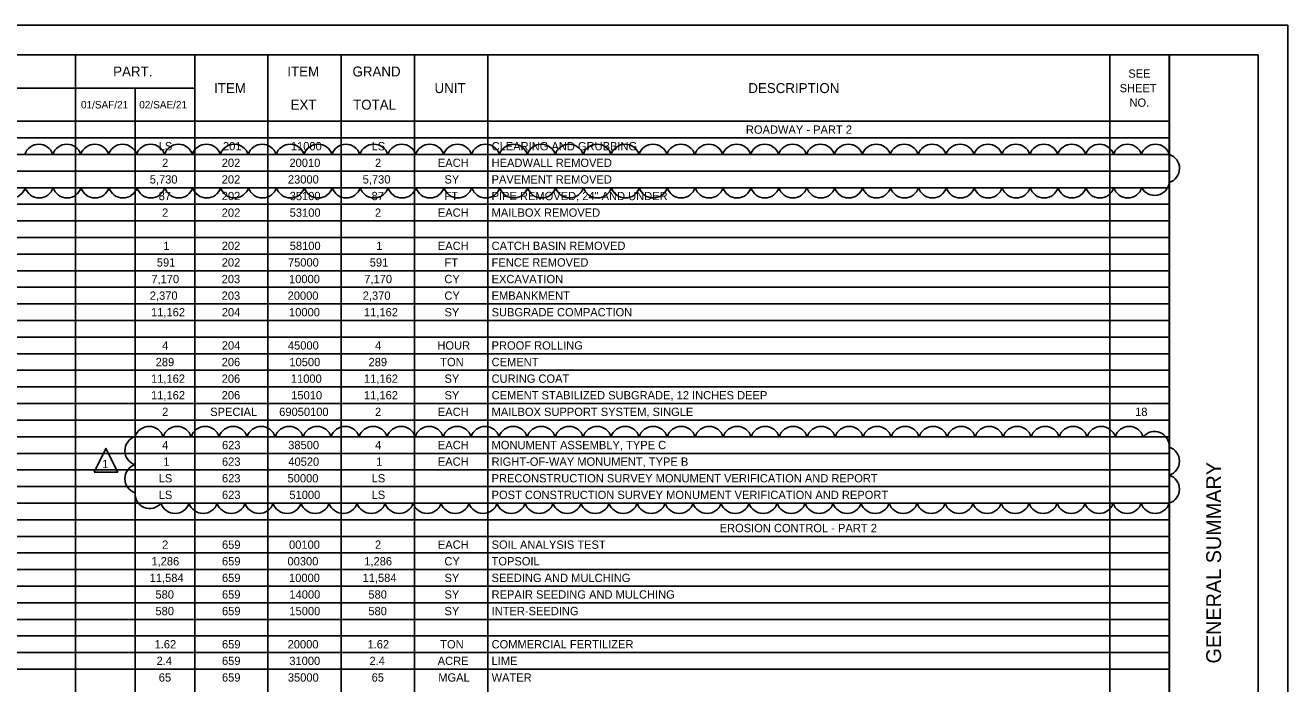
# Model space of a CAD drawing. Extents: x -156 to 77, y 0 to 24.
# Drawn here: x 12.71 to 34, y 10.89 to 22 of the extents above; entities that cross this region are included whole.
import ezdxf

# ---------------------------------------------------------------- set-up
doc = ezdxf.new("R2010")
doc.units = 0
for name, color, linetype in [('Default', 7, 'Continuous'), ('MU_Markup_Cloud', 7, 'Continuous'), ('SH_Border', 7, 'Continuous'), ('SH_Cut_Line', 7, 'Continuous'), ('SH_Data', 7, 'Continuous')]:
    doc.layers.add(name, color=color, linetype=linetype)

msp = doc.modelspace()

# ---------------------------------------------------------------- linework, layer by layer
at = {"layer": 'Default'}
for p, q in [((1.5, 21.5), (32.004, 21.5)), ((13.556, 21.5), (13.556, 0.5)), ((15.566, 21.5), (15.566, 0.5)), ((16.801, 21.5), (16.801, 0.5)), ((18.036, 21.5), (18.036, 0.5)), ((19.272, 21.5), (19.272, 0.5)), ((20.507, 21.5), (20.507, 0.5)), ((30.999, 21.5), (30.999, 0.5)), ((32.004, 21.5), (32.004, 0.5)), ((1.5, 20.94), (15.566, 20.94)), ((14.561, 20.94), (14.561, 0.5)), ((1.5, 20.38), (32.004, 20.38)), ((1.5, 20.1), (32.004, 20.1)), ((1.5, 19.82), (32.004, 19.82)), ((1.5, 19.54), (32.004, 19.54)), ((1.5, 19.26), (32.004, 19.26)), ((1.5, 18.98), (32.004, 18.98)), ((1.5, 18.7), (32.004, 18.7)), ((1.5, 18.42), (32.004, 18.42)), ((1.5, 18.14), (32.004, 18.14)), ((1.5, 17.86), (32.004, 17.86)), ((1.5, 17.58), (32.004, 17.58)), ((1.5, 17.3), (32.004, 17.3)), ((1.5, 17.02), (32.004, 17.02)), ((1.5, 16.74), (32.004, 16.74)), ((1.5, 16.46), (32.004, 16.46)), ((1.5, 16.18), (32.004, 16.18)), ((1.5, 15.9), (32.004, 15.9)), ((1.5, 15.62), (32.004, 15.62)), ((1.5, 15.34), (32.004, 15.34)), ((1.5, 15.06), (32.004, 15.06)), ((1.5, 14.78), (32.004, 14.78)), ((1.5, 14.5), (32.004, 14.5)), ((1.5, 14.22), (32.004, 14.22)), ((1.5, 13.94), (32.004, 13.94)), ((1.5, 13.66), (32.004, 13.66)), ((1.5, 13.38), (32.004, 13.38)), ((1.5, 13.1), (32.004, 13.1)), ((1.5, 12.82), (32.004, 12.82)), ((1.5, 12.54), (32.004, 12.54)), ((1.5, 12.26), (32.004, 12.26)), ((1.5, 11.98), (32.004, 11.98)), ((1.5, 11.7), (32.004, 11.7)), ((1.5, 11.42), (32.004, 11.42)), ((1.5, 11.14), (32.004, 11.14))]:
    msp.add_line(p, q, dxfattribs=at)
at = {"layer": 'MU_Markup_Cloud'}
msp.add_lwpolyline([(13.869, 14.464), (14.069, 14.864), (14.269, 14.464)], close=True, dxfattribs=at)
for centre, radius, start, end in [((12.938, 19.746), 0.247, 17.5, 162.5), ((13.409, 19.746), 0.247, 17.5, 162.5), ((13.88, 19.746), 0.247, 17.5, 162.5), ((14.35, 19.746), 0.247, 17.5, 162.5), ((14.821, 19.746), 0.247, 17.5, 162.5), ((15.292, 19.746), 0.247, 17.5, 162.5), ((15.763, 19.746), 0.247, 17.5, 162.5), ((16.233, 19.746), 0.247, 17.5, 162.5), ((16.704, 19.746), 0.247, 17.5, 162.5), ((17.175, 19.746), 0.247, 17.5, 162.5), ((17.646, 19.746), 0.247, 17.5, 162.5), ((18.116, 19.746), 0.247, 17.5, 162.5), ((18.587, 19.746), 0.247, 17.5, 162.5), ((19.058, 19.746), 0.247, 17.5, 162.5), ((19.529, 19.746), 0.247, 17.5, 162.5), ((19.999, 19.746), 0.247, 17.5, 162.5), ((20.47, 19.746), 0.247, 17.5, 162.5), ((20.941, 19.746), 0.247, 17.5, 162.5), ((21.412, 19.746), 0.247, 17.5, 162.5), ((21.882, 19.746), 0.247, 17.5, 162.5), ((22.353, 19.746), 0.247, 17.5, 162.5), ((22.824, 19.746), 0.247, 17.5, 162.5), ((23.295, 19.746), 0.247, 17.5, 162.5), ((23.765, 19.746), 0.247, 17.5, 162.5), ((24.236, 19.746), 0.247, 17.5, 162.5), ((24.707, 19.746), 0.247, 17.5, 162.5), ((25.178, 19.746), 0.247, 17.5, 162.5), ((25.648, 19.746), 0.247, 17.5, 162.5), ((26.119, 19.746), 0.247, 17.5, 162.5), ((26.59, 19.746), 0.247, 17.5, 162.5), ((27.061, 19.746), 0.247, 17.5, 162.5), ((27.531, 19.746), 0.247, 17.5, 162.5), ((28.002, 19.746), 0.247, 17.5, 162.5), ((28.473, 19.746), 0.247, 17.5, 162.5), ((28.944, 19.746), 0.247, 17.5, 162.5), ((29.414, 19.746), 0.247, 17.5, 162.5), ((29.885, 19.746), 0.247, 17.5, 162.5), ((30.356, 19.746), 0.247, 17.5, 162.5), ((30.827, 19.746), 0.247, 17.5, 162.5), ((31.297, 19.746), 0.247, 17.5, 162.5), ((31.768, 19.746), 0.247, 17.5, 162.5), ((31.928, 19.585), 0.247, 287.1367, 72.1367), ((12.473, 19.334), 0.247, 197.5, 342.5), ((12.944, 19.334), 0.247, 197.5, 342.5), ((13.414, 19.334), 0.247, 197.5, 342.5), ((13.885, 19.334), 0.247, 197.5, 342.5), ((14.356, 19.334), 0.247, 197.5, 342.5), ((14.827, 19.334), 0.247, 197.5, 342.5), ((15.297, 19.334), 0.247, 197.5, 342.5), ((15.768, 19.334), 0.247, 197.5, 342.5), ((16.239, 19.334), 0.247, 197.5, 342.5), ((16.71, 19.334), 0.247, 197.5, 342.5), ((17.18, 19.334), 0.247, 197.5, 342.5), ((17.651, 19.334), 0.247, 197.5, 342.5), ((18.122, 19.334), 0.247, 197.5, 342.5), ((18.593, 19.334), 0.247, 197.5, 342.5), ((19.063, 19.334), 0.247, 197.5, 342.5), ((19.534, 19.334), 0.247, 197.5, 342.5), ((20.005, 19.334), 0.247, 197.5, 342.5), ((20.476, 19.334), 0.247, 197.5, 342.5), ((20.946, 19.334), 0.247, 197.5, 342.5), ((21.417, 19.334), 0.247, 197.5, 342.5), ((21.888, 19.334), 0.247, 197.5, 342.5), ((22.359, 19.334), 0.247, 197.5, 342.5), ((22.829, 19.334), 0.247, 197.5, 342.5), ((23.3, 19.334), 0.247, 197.5, 342.5), ((23.771, 19.334), 0.247, 197.5, 342.5), ((24.242, 19.334), 0.247, 197.5, 342.5), ((24.712, 19.334), 0.247, 197.5, 342.5), ((25.183, 19.334), 0.247, 197.5, 342.5), ((25.654, 19.334), 0.247, 197.5, 342.5), ((26.125, 19.334), 0.247, 197.5, 342.5), ((26.595, 19.334), 0.247, 197.5, 342.5), ((27.066, 19.334), 0.247, 197.5, 342.5), ((27.537, 19.334), 0.247, 197.5, 342.5), ((28.008, 19.334), 0.247, 197.5, 342.5), ((28.478, 19.334), 0.247, 197.5, 342.5), ((28.949, 19.334), 0.247, 197.5, 342.5), ((29.42, 19.334), 0.247, 197.5, 342.5), ((29.891, 19.334), 0.247, 197.5, 342.5), ((30.361, 19.334), 0.247, 197.5, 342.5), ((30.832, 19.334), 0.247, 197.5, 342.5), ((31.303, 19.334), 0.247, 197.5, 342.5), ((31.755, 19.377), 0.247, 208.4302, 353.4302), ((14.797, 14.986), 0.248, 17.5, 162.5), ((15.27, 14.986), 0.248, 17.5, 162.5), ((15.742, 14.986), 0.248, 17.5, 162.5), ((16.214, 14.986), 0.248, 17.5, 162.5), ((16.686, 14.986), 0.248, 17.5, 162.5), ((17.159, 14.986), 0.248, 17.5, 162.5), ((17.631, 14.986), 0.248, 17.5, 162.5), ((18.103, 14.986), 0.248, 17.5, 162.5), ((18.575, 14.986), 0.248, 17.5, 162.5), ((19.047, 14.986), 0.248, 17.5, 162.5), ((19.52, 14.986), 0.248, 17.5, 162.5), ((19.992, 14.986), 0.248, 17.5, 162.5), ((20.464, 14.986), 0.248, 17.5, 162.5), ((20.936, 14.986), 0.248, 17.5, 162.5), ((21.409, 14.986), 0.248, 17.5, 162.5), ((21.881, 14.986), 0.248, 17.5, 162.5), ((22.353, 14.986), 0.248, 17.5, 162.5), ((22.825, 14.986), 0.248, 17.5, 162.5), ((23.298, 14.986), 0.248, 17.5, 162.5), ((23.77, 14.986), 0.248, 17.5, 162.5), ((24.242, 14.986), 0.248, 17.5, 162.5), ((24.714, 14.986), 0.248, 17.5, 162.5), ((25.187, 14.986), 0.248, 17.5, 162.5), ((25.659, 14.986), 0.248, 17.5, 162.5), ((26.131, 14.986), 0.248, 17.5, 162.5), ((26.603, 14.986), 0.248, 17.5, 162.5), ((27.076, 14.986), 0.248, 17.5, 162.5), ((27.548, 14.986), 0.248, 17.5, 162.5), ((28.02, 14.986), 0.248, 17.5, 162.5), ((28.492, 14.986), 0.248, 17.5, 162.5), ((28.965, 14.986), 0.248, 17.5, 162.5), ((29.437, 14.986), 0.248, 17.5, 162.5), ((29.909, 14.986), 0.248, 17.5, 162.5), ((30.381, 14.986), 0.248, 17.5, 162.5), ((30.854, 14.986), 0.248, 17.5, 162.5), ((31.326, 14.986), 0.248, 17.5, 162.5), ((31.753, 14.903), 0.247, 355.6683, 140.6683), ((14.636, 14.824), 0.248, 107.5, 252.5), ((31.926, 14.648), 0.248, 287.5, 72.5), ((14.636, 14.352), 0.248, 107.5, 252.5), ((31.926, 14.176), 0.248, 287.5, 72.5), ((14.808, 14.097), 0.247, 175.6683, 320.6683), ((15.235, 14.014), 0.248, 197.5, 342.5), ((15.708, 14.014), 0.248, 197.5, 342.5), ((16.18, 14.014), 0.248, 197.5, 342.5), ((16.652, 14.014), 0.248, 197.5, 342.5), ((17.124, 14.014), 0.248, 197.5, 342.5), ((17.597, 14.014), 0.248, 197.5, 342.5), ((18.069, 14.014), 0.248, 197.5, 342.5), ((18.541, 14.014), 0.248, 197.5, 342.5), ((19.013, 14.014), 0.248, 197.5, 342.5), ((19.486, 14.014), 0.248, 197.5, 342.5), ((19.958, 14.014), 0.248, 197.5, 342.5), ((20.43, 14.014), 0.248, 197.5, 342.5), ((20.902, 14.014), 0.248, 197.5, 342.5), ((21.375, 14.014), 0.248, 197.5, 342.5), ((21.847, 14.014), 0.248, 197.5, 342.5), ((22.319, 14.014), 0.248, 197.5, 342.5), ((22.791, 14.014), 0.248, 197.5, 342.5), ((23.264, 14.014), 0.248, 197.5, 342.5), ((23.736, 14.014), 0.248, 197.5, 342.5), ((24.208, 14.014), 0.248, 197.5, 342.5), ((24.68, 14.014), 0.248, 197.5, 342.5), ((25.152, 14.014), 0.248, 197.5, 342.5), ((25.625, 14.014), 0.248, 197.5, 342.5), ((26.097, 14.014), 0.248, 197.5, 342.5), ((26.569, 14.014), 0.248, 197.5, 342.5), ((27.041, 14.014), 0.248, 197.5, 342.5), ((27.514, 14.014), 0.248, 197.5, 342.5), ((27.986, 14.014), 0.248, 197.5, 342.5), ((28.458, 14.014), 0.248, 197.5, 342.5), ((28.93, 14.014), 0.248, 197.5, 342.5), ((29.403, 14.014), 0.248, 197.5, 342.5), ((29.875, 14.014), 0.248, 197.5, 342.5), ((30.347, 14.014), 0.248, 197.5, 342.5), ((30.819, 14.014), 0.248, 197.5, 342.5), ((31.292, 14.014), 0.248, 197.5, 342.5), ((31.764, 14.014), 0.248, 197.5, 342.5)]:
    msp.add_arc(centre, radius, start, end, dxfattribs=at)
at = {"layer": 'SH_Border'}
msp.add_line((32, 0.5), (32, 21.5), dxfattribs=at)
msp.add_lwpolyline([(1.5, 21.5), (33.5, 21.5), (33.5, 0.5), (1.5, 0.5)], close=True, dxfattribs=at)
at = {"layer": 'SH_Cut_Line'}
msp.add_lwpolyline([(0, 0), (34, 0), (34, 22), (0, 22)], close=True, dxfattribs=at)

# ---------------------------------------------------------------- texts
at = {"layer": 'Default'}
for s, height, p in [('PART.', 0.168, (14.191, 21.136)), ('ITEM', 0.168, (17.128, 21.136)), ('GRAND', 0.168, (18.227, 21.136)), ('SEE ', 0.14, (31.311, 21.115)), ('ITEM', 0.168, (15.893, 20.856)), ('UNIT', 0.168, (19.61, 20.856)), ('DESCRIPTION', 0.168, (24.903, 20.856)), ('SHEET ', 0.14, (31.165, 20.87)), ('01/SAF/21', 0.126, (13.648, 20.597)), ('02/SAE/21', 0.126, (14.631, 20.597)), ('EXT', 0.168, (17.183, 20.576)), ('TOTAL', 0.168, (18.237, 20.576)), ('NO.', 0.14, (31.331, 20.625)), ('ROADWAY - PART 2', 0.14, (24.862, 20.17)), ('LS', 0.14, (14.959, 19.89)), ('201', 0.14, (16.043, 19.89)), ('11000', 0.14, (17.188, 19.89)), ('LS', 0.14, (18.55, 19.89)), ('CLEARING AND GRUBBING', 0.14, (20.573, 19.89)), ('2', 0.14, (15.016, 19.61)), ('202', 0.14, (16.022, 19.61)), ('20010', 0.14, (17.164, 19.61)), ('2', 0.14, (18.607, 19.61)), ('EACH', 0.14, (19.667, 19.61)), ('HEADWALL REMOVED', 0.14, (20.573, 19.61)), ('5,730', 0.14, (14.808, 19.33)), ('202', 0.14, (16.022, 19.33)), ('23000', 0.14, (17.138, 19.33)), ('5,730', 0.14, (18.399, 19.33)), ('SY', 0.14, (19.779, 19.33)), ('PAVEMENT REMOVED', 0.14, (20.573, 19.33)), ('87', 0.14, (14.958, 19.05)), ('202', 0.14, (16.022, 19.05)), ('35100', 0.14, (17.168, 19.05)), ('87', 0.14, (18.548, 19.05)), ('FT', 0.14, (19.779, 19.05)), ('PIPE REMOVED, 24" AND UNDER', 0.14, (20.573, 19.05)), ('2', 0.14, (15.016, 18.77)), ('202', 0.14, (16.022, 18.77)), ('53100', 0.14, (17.168, 18.77)), ('2', 0.14, (18.607, 18.77)), ('EACH', 0.14, (19.667, 18.77)), ('MAILBOX REMOVED', 0.14, (20.573, 18.77)), ('1', 0.14, (15.037, 18.21)), ('202', 0.14, (16.022, 18.21)), ('58100', 0.14, (17.169, 18.21)), ('1', 0.14, (18.628, 18.21)), ('EACH', 0.14, (19.667, 18.21)), ('CATCH BASIN REMOVED', 0.14, (20.573, 18.21)), ('591', 0.14, (14.927, 17.93)), ('202', 0.14, (16.022, 17.93)), ('75000', 0.14, (17.139, 17.93)), ('591', 0.14, (18.518, 17.93)), ('FT', 0.14, (19.779, 17.93)), ('FENCE REMOVED', 0.14, (20.573, 17.93)), ('7,170', 0.14, (14.835, 17.65)), ('203', 0.14, (16.021, 17.65)), ('10000', 0.14, (17.157, 17.65)), ('7,170', 0.14, (18.426, 17.65)), ('CY', 0.14, (19.777, 17.65)), ('EXCAVATION', 0.14, (20.573, 17.65)), ('2,370', 0.14, (14.809, 17.37)), ('203', 0.14, (16.021, 17.37)), ('20000', 0.14, (17.133, 17.37)), ('2,370', 0.14, (18.4, 17.37)), ('CY', 0.14, (19.777, 17.37)), ('EMBANKMENT', 0.14, (20.573, 17.37)), ('11,162', 0.14, (14.83, 17.09)), ('204', 0.14, (16.023, 17.09)), ('10000', 0.14, (17.157, 17.09)), ('11,162', 0.14, (18.421, 17.09)), ('SY', 0.14, (19.779, 17.09)), ('SUBGRADE COMPACTION', 0.14, (20.573, 17.09)), ('4', 0.14, (15.017, 16.53)), ('204', 0.14, (16.023, 16.53)), ('45000', 0.14, (17.138, 16.53)), ('4', 0.14, (18.608, 16.53)), ('HOUR', 0.14, (19.659, 16.53)), ('PROOF ROLLING', 0.14, (20.573, 16.53)), ('289', 0.14, (14.908, 16.25)), ('206', 0.14, (16.021, 16.25)), ('10500', 0.14, (17.163, 16.25)), ('289', 0.14, (18.498, 16.25)), ('TON', 0.14, (19.707, 16.25)), ('CEMENT', 0.14, (20.573, 16.25)), ('11,162', 0.14, (14.83, 15.97)), ('206', 0.14, (16.021, 15.97)), ('11000', 0.14, (17.188, 15.97)), ('11,162', 0.14, (18.421, 15.97)), ('SY', 0.14, (19.779, 15.97)), ('CURING COAT', 0.14, (20.573, 15.97)), ('11,162', 0.14, (14.83, 15.69)), ('206', 0.14, (16.021, 15.69)), ('15010', 0.14, (17.194, 15.69)), ('11,162', 0.14, (18.421, 15.69)), ('SY', 0.14, (19.779, 15.69)), ('CEMENT STABILIZED SUBGRADE, 12 INCHES DEEP', 0.14, (20.573, 15.69)), ('2', 0.14, (15.016, 15.41)), ('SPECIAL', 0.14, (15.828, 15.41)), ('69050100', 0.14, (16.991, 15.41)), ('2', 0.14, (18.607, 15.41)), ('EACH', 0.14, (19.667, 15.41)), ('MAILBOX SUPPORT SYSTEM, SINGLE', 0.14, (20.573, 15.41)), ('18', 0.14, (31.426, 15.41)), ('4', 0.14, (15.017, 14.85)), ('623', 0.14, (16.026, 14.85)), ('38500', 0.14, (17.143, 14.85)), ('4', 0.14, (18.608, 14.85)), ('EACH', 0.14, (19.667, 14.85)), ('MONUMENT ASSEMBLY, TYPE C', 0.14, (20.573, 14.85)), ('1', 0.14, (15.037, 14.57)), ('623', 0.14, (16.026, 14.57)), ('40520', 0.14, (17.145, 14.57)), ('1', 0.14, (18.628, 14.57)), ('EACH', 0.14, (19.667, 14.57)), ('RIGHT-OF-WAY MONUMENT, TYPE B', 0.14, (20.573, 14.57)), ('LS', 0.14, (14.959, 14.29)), ('623', 0.14, (16.026, 14.29)), ('50000', 0.14, (17.132, 14.29)), ('LS', 0.14, (18.55, 14.29)), ('PRECONSTRUCTION SURVEY MONUMENT VERIFICATION AND REPORT', 0.14, (20.573, 14.29)), ('LS', 0.14, (14.959, 14.01)), ('623', 0.14, (16.026, 14.01)), ('51000', 0.14, (17.163, 14.01)), ('LS', 0.14, (18.55, 14.01)), ('POST CONSTRUCTION SURVEY MONUMENT VERIFICATION AND REPORT', 0.14, (20.573, 14.01)), ('EROSION CONTROL - PART 2', 0.14, (24.419, 13.45)), ('2', 0.14, (15.016, 13.17)), ('659', 0.14, (16.026, 13.17)), ('00100', 0.14, (17.157, 13.17)), ('2', 0.14, (18.607, 13.17)), ('EACH', 0.14, (19.667, 13.17)), ('SOIL ANALYSIS TEST', 0.14, (20.573, 13.17)), ('1,286', 0.14, (14.836, 12.89)), ('659', 0.14, (16.026, 12.89)), ('00300', 0.14, (17.131, 12.89)), ('1,286', 0.14, (18.426, 12.89)), ('CY', 0.14, (19.777, 12.89)), ('TOPSOIL', 0.14, (20.573, 12.89)), ('11,584', 0.14, (14.807, 12.61)), ('659', 0.14, (16.026, 12.61)), ('10000', 0.14, (17.157, 12.61)), ('11,584', 0.14, (18.397, 12.61)), ('SY', 0.14, (19.779, 12.61)), ('SEEDING AND MULCHING', 0.14, (20.573, 12.61)), ('580', 0.14, (14.904, 12.33)), ('659', 0.14, (16.026, 12.33)), ('14000', 0.14, (17.163, 12.33)), ('580', 0.14, (18.495, 12.33)), ('SY', 0.14, (19.779, 12.33)), ('REPAIR SEEDING AND MULCHING', 0.14, (20.573, 12.33)), ('580', 0.14, (14.904, 12.05)), ('659', 0.14, (16.026, 12.05)), ('15000', 0.14, (17.163, 12.05)), ('580', 0.14, (18.495, 12.05)), ('SY', 0.14, (19.779, 12.05)), ('INTER-SEEDING', 0.14, (20.573, 12.05)), ('1.62', 0.14, (14.89, 11.49)), ('659', 0.14, (16.026, 11.49)), ('20000', 0.14, (17.133, 11.49)), ('1.62', 0.14, (18.481, 11.49)), ('TON', 0.14, (19.707, 11.49)), ('COMMERCIAL FERTILIZER', 0.14, (20.573, 11.49)), ('2.4', 0.14, (14.923, 11.21)), ('659', 0.14, (16.026, 11.21)), ('31000', 0.14, (17.162, 11.21)), ('2.4', 0.14, (18.513, 11.21)), ('ACRE', 0.14, (19.664, 11.21)), ('LIME', 0.14, (20.573, 11.21)), ('65', 0.14, (14.96, 10.93)), ('659', 0.14, (16.026, 10.93)), ('35000', 0.14, (17.137, 10.93)), ('65', 0.14, (18.55, 10.93)), ('MGAL', 0.14, (19.674, 10.93)), ('WATER', 0.14, (20.573, 10.93))]:
    msp.add_text(s, height=height, dxfattribs=at).set_placement(p)
at = {"layer": 'MU_Markup_Cloud'}
msp.add_text('1', height=0.14, dxfattribs=at).set_placement((14.006, 14.53))
at = {"layer": 'SH_Data'}
msp.add_text('GENERAL SUMMARY', height=0.25, rotation=90, dxfattribs=at).set_placement((32.875, 11.235))

doc.saveas('drawing.dxf')
